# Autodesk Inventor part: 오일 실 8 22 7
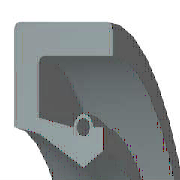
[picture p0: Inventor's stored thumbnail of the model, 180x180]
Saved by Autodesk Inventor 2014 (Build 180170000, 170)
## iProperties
IsCustomPart: 1
Created: 2012-02
Part Number: 오일 실 8 22 7
Material: 고무
Description: 오일-실
Document SubType Name: Modeling
Standard: KS B 2804
Designer: test
Standards Organization: KS
Language: ko-KR
Size Designation: S - 8 22 7
Categories: <MemberInstance><Categories><Category DisplayName="샤프트 부품" InternalName="7f7aeb1f-a693-4053-b835-cee3144e0d98" Mnemonic="SHFT"><Category DisplayName="실링" Intern
Density: 0.93 g/cm^3
Mass: 1.07912 g
Surface Area: 17.6852 cm^2
Volume: 1.16034 cm^3
Appearance: 고무 - 검은색 - 버전 1.1
Author: test
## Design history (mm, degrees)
revolve "본체" stored, may be unused: angle "d17" = 90 deg
revolve "스프링1" stored, may be unused: angle "d18" = 90 deg
body "Solid1"
sketch "스케치1"
  geometry: L1 (0, 11)-(7, 11); L2 (7, 11)-(7, 9.75); L3 (7, 9.75)-(1.75, 9.75); L4 (0, 11)-(0, 6.1); L5 (0, 6.1)-(1.75, 5.75); L6 (1.75, 5.75)-(4.9, 4); L7 (4.9, 4)-(0, 4); L8 (6.3, 4.875)-(6.3, 6.1); L9 (0, 0)-(9.586, 0) reference; L10 (4.9, 4)-(6.3, 4.875); L11 (0, 18)-(0, -3) reference; L12 (-1.917, 0)-(11.503, 0) reference; L13 (4.2, 6.1)-(1.75, 6.59); L14 (1.75, 6.59)-(1.75, 9.75); L15 (6.3, 6.1)-(5.6, 6.1); C1 r 0.455 at (4.9, 6.1); A1 r 0.7 centre (4.9, 6.1) between (5.6, 6.1) and (4.2, 6.1)
  constraints: 26 end point, 5 horizontal alignment, 4 perpendicular, 2 centre point, 2 collinear, 2 horizontal, 2 parallel, 2 point on circle, 2 point on line, 2 vertical alignment, 1 coincident
  dimensions: "d0" = 22 diameter of L1 L9 (= SD2); "d1" = 9.75 diameter of L8.start L9 (= ABDM); "d2" = 1.25 distance of L1.end L2.end (computed from SD); "d3" = 0.91 diameter of C1 (= SPDI); "d4" = 1.4 diameter of A1 (= SPDA); "d5" = 8 diameter of L6.end L9 (= NND); "d6" = 11.5 diameter of L5.end L9 (= TKDM); "d7" = 12.2 diameter of L4.end L9 (= HLDM); "d8" = 4.9 distance from line of C1.centre L4 (= SPDST); "d9" = 6.3 distance between parallel lines of L8 L4 (= SDI); "d10" = 7 distance between parallel lines of L2 L4 (= SWDT); "d12" = 1.75 distance between parallel lines of L14 L4 (= SD)
fillet "모깎기1" dims "d11" = 0.3 (= RR)
other parameters: "SD2" = 22 [user parameter; used in 1 equation term], "SWDT" = 7 [user parameter; used in 1 equation term], "RR" = 0.3 [user parameter; used in 1 equation term], "SD" = 1.75 [user parameter; used in 2 equation terms], "NND" = 8 [user parameter; used in 1 equation term], "SPDA" = 1.4 [user parameter; used in 1 equation term], "SPDI" = 0.91 [user parameter; used in 1 equation term], "TKDM" = 11.5 [user parameter; used in 1 equation term], "HLDM" = 12.2 [user parameter; used in 1 equation term], "ABDM" = 9.75 [user parameter; used in 1 equation term], "SDI" = 6.3 [user parameter; used in 1 equation term], "SPDST" = 4.9 [user parameter; used in 1 equation term], "d13" = 0, "d14" = 0, "d15" = 0, "LAB" = 0.35 [user parameter]
